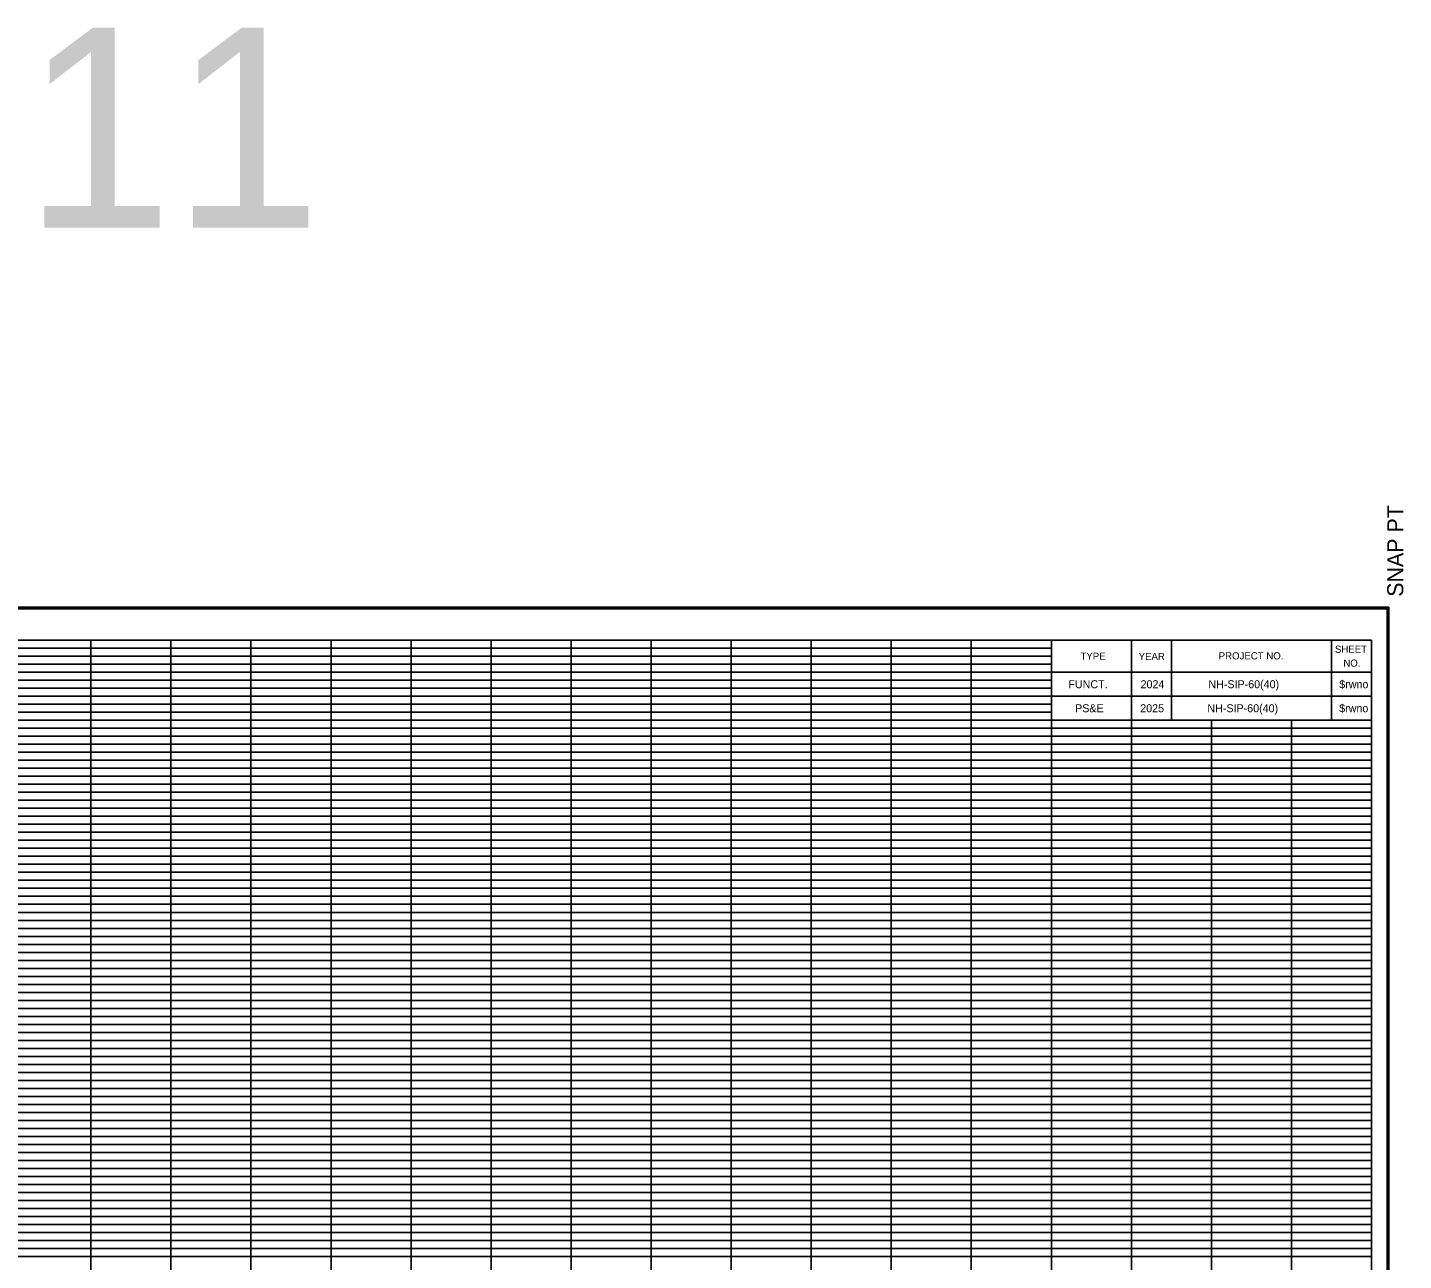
# Model space of a CAD drawing. Extents: x 2313580 to 2322968, y 282099 to 303247.
# Drawn here: x 2316394.2 to 2316738.1, y 287852.7 to 288160.8 of the extents above; entities that cross this region are included whole.
import ezdxf

# ---------------------------------------------------------------- set-up
doc = ezdxf.new("R2010")
doc.units = 0
for name, color, linetype in [('DESIGN - SCRATCH - User 1', 7, 'Continuous'), ('DESIGN - SHEET - Corner Text', 7, 'Continuous'), ('DESIGN - SHEET - Light Grid', 7, 'Continuous'), ('DESIGN - SHEET - Linework', 7, 'Continuous'), ('DESIGN - SHEET - Plot Shape', 7, 'Continuous')]:
    doc.layers.add(name, color=color, linetype=linetype)

msp = doc.modelspace()

# ---------------------------------------------------------------- linework, layer by layer
at = {"layer": 'DESIGN - SCRATCH - User 1'}
for p, q in [((2316660.08, 287996.67), (2316660.08, 287996.67)), ((2316674.88, 287996.67), (2316674.88, 287996.67)), ((2316699.88, 287996.67), (2316699.88, 287996.67)), ((2316724.88, 287996.67), (2316724.88, 287996.67)), ((2316660.08, 287990.67), (2316660.08, 287990.67)), ((2316674.88, 287990.67), (2316674.88, 287990.67)), ((2316699.88, 287990.67), (2316699.88, 287990.67)), ((2316724.88, 287990.67), (2316724.88, 287990.67))]:
    msp.add_line(p, q, dxfattribs=at)
at = {"layer": 'DESIGN - SHEET - Light Grid'}
for p, q in [((2316250.08, 288005.67), (2316410.08, 288005.67)), ((2316410.08, 288005.67), (2316570.08, 288005.67)), ((2316570.08, 288005.67), (2316650.08, 288005.67)), ((2316250.08, 288003.67), (2316410.08, 288003.67)), ((2316250.08, 288001.67), (2316410.08, 288001.67)), ((2316410.08, 288003.67), (2316570.08, 288003.67)), ((2316410.08, 288001.67), (2316570.08, 288001.67)), ((2316570.08, 288003.67), (2316650.08, 288003.67)), ((2316570.08, 288001.67), (2316650.08, 288001.67)), ((2316250.08, 287999.67), (2316410.08, 287999.67)), ((2316250.08, 287997.67), (2316410.08, 287997.67)), ((2316410.08, 287999.67), (2316570.08, 287999.67)), ((2316410.08, 287997.67), (2316570.08, 287997.67)), ((2316570.08, 287999.67), (2316650.08, 287999.67)), ((2316570.08, 287997.67), (2316650.08, 287997.67)), ((2316250.08, 287995.67), (2316410.08, 287995.67)), ((2316410.08, 287995.67), (2316570.08, 287995.67)), ((2316570.08, 287995.67), (2316650.08, 287995.67)), ((2316250.08, 287993.67), (2316410.08, 287993.67)), ((2316250.08, 287991.67), (2316410.08, 287991.67)), ((2316410.08, 287993.67), (2316570.08, 287993.67)), ((2316410.08, 287991.67), (2316570.08, 287991.67)), ((2316570.08, 287993.67), (2316650.08, 287993.67)), ((2316570.08, 287991.67), (2316650.08, 287991.67)), ((2316250.08, 287989.67), (2316410.08, 287989.67)), ((2316410.08, 287989.67), (2316570.08, 287989.67)), ((2316570.08, 287989.67), (2316650.08, 287989.67)), ((2316250.08, 287985.67), (2316410.08, 287985.67)), ((2316250.08, 287983.67), (2316410.08, 287983.67)), ((2316410.08, 287985.67), (2316570.08, 287985.67)), ((2316410.08, 287983.67), (2316570.08, 287983.67)), ((2316570.08, 287985.67), (2316730.08, 287985.67)), ((2316570.08, 287983.67), (2316730.08, 287983.67)), ((2316250.08, 287981.67), (2316410.08, 287981.67)), ((2316410.08, 287981.67), (2316570.08, 287981.67)), ((2316570.08, 287981.67), (2316730.08, 287981.67)), ((2316250.08, 287979.67), (2316410.08, 287979.67)), ((2316250.08, 287977.67), (2316410.08, 287977.67)), ((2316410.08, 287979.67), (2316570.08, 287979.67)), ((2316410.08, 287977.67), (2316570.08, 287977.67)), ((2316570.08, 287979.67), (2316730.08, 287979.67)), ((2316570.08, 287977.67), (2316730.08, 287977.67)), ((2316250.08, 287975.67), (2316410.08, 287975.67)), ((2316250.08, 287973.67), (2316410.08, 287973.67)), ((2316410.08, 287975.67), (2316570.08, 287975.67)), ((2316410.08, 287973.67), (2316570.08, 287973.67)), ((2316570.08, 287975.67), (2316730.08, 287975.67)), ((2316570.08, 287973.67), (2316730.08, 287973.67)), ((2316250.08, 287971.67), (2316410.08, 287971.67)), ((2316250.08, 287969.67), (2316410.08, 287969.67)), ((2316410.08, 287971.67), (2316570.08, 287971.67)), ((2316410.08, 287969.67), (2316570.08, 287969.67)), ((2316570.08, 287971.67), (2316730.08, 287971.67)), ((2316570.08, 287969.67), (2316730.08, 287969.67)), ((2316250.08, 287965.67), (2316410.08, 287965.67)), ((2316250.08, 287963.67), (2316410.08, 287963.67)), ((2316410.08, 287965.67), (2316570.08, 287965.67)), ((2316410.08, 287963.67), (2316570.08, 287963.67)), ((2316570.08, 287965.67), (2316730.08, 287965.67)), ((2316570.08, 287963.67), (2316730.08, 287963.67)), ((2316250.08, 287961.67), (2316410.08, 287961.67)), ((2316250.08, 287959.67), (2316410.08, 287959.67)), ((2316410.08, 287961.67), (2316570.08, 287961.67)), ((2316410.08, 287959.67), (2316570.08, 287959.67)), ((2316570.08, 287961.67), (2316730.08, 287961.67)), ((2316570.08, 287959.67), (2316730.08, 287959.67)), ((2316250.08, 287957.67), (2316410.08, 287957.67)), ((2316410.08, 287957.67), (2316570.08, 287957.67)), ((2316570.08, 287957.67), (2316730.08, 287957.67)), ((2316250.08, 287955.67), (2316410.08, 287955.67)), ((2316250.08, 287953.67), (2316410.08, 287953.67)), ((2316410.08, 287955.67), (2316570.08, 287955.67)), ((2316410.08, 287953.67), (2316570.08, 287953.67)), ((2316570.08, 287955.67), (2316730.08, 287955.67)), ((2316570.08, 287953.67), (2316730.08, 287953.67)), ((2316250.08, 287951.67), (2316410.08, 287951.67)), ((2316250.08, 287949.67), (2316410.08, 287949.67)), ((2316410.08, 287951.67), (2316570.08, 287951.67)), ((2316410.08, 287949.67), (2316570.08, 287949.67)), ((2316570.08, 287951.67), (2316730.08, 287951.67)), ((2316570.08, 287949.67), (2316730.08, 287949.67)), ((2316250.08, 287945.67), (2316410.08, 287945.67)), ((2316410.08, 287945.67), (2316570.08, 287945.67)), ((2316570.08, 287945.67), (2316730.08, 287945.67)), ((2316250.08, 287943.67), (2316410.08, 287943.67)), ((2316410.08, 287943.67), (2316570.08, 287943.67)), ((2316570.08, 287943.67), (2316730.08, 287943.67)), ((2316250.08, 287941.67), (2316410.08, 287941.67)), ((2316250.08, 287939.67), (2316410.08, 287939.67)), ((2316410.08, 287941.67), (2316570.08, 287941.67)), ((2316410.08, 287939.67), (2316570.08, 287939.67)), ((2316570.08, 287941.67), (2316730.08, 287941.67)), ((2316570.08, 287939.67), (2316730.08, 287939.67)), ((2316250.08, 287937.67), (2316410.08, 287937.67)), ((2316250.08, 287935.67), (2316410.08, 287935.67)), ((2316410.08, 287937.67), (2316570.08, 287937.67)), ((2316410.08, 287935.67), (2316570.08, 287935.67)), ((2316570.08, 287937.67), (2316730.08, 287937.67)), ((2316570.08, 287935.67), (2316730.08, 287935.67)), ((2316250.08, 287933.67), (2316410.08, 287933.67)), ((2316410.08, 287933.67), (2316570.08, 287933.67)), ((2316570.08, 287933.67), (2316730.08, 287933.67)), ((2316250.08, 287931.67), (2316410.08, 287931.67)), ((2316250.08, 287929.67), (2316410.08, 287929.67)), ((2316410.08, 287931.67), (2316570.08, 287931.67)), ((2316410.08, 287929.67), (2316570.08, 287929.67)), ((2316570.08, 287931.67), (2316730.08, 287931.67)), ((2316570.08, 287929.67), (2316730.08, 287929.67)), ((2316250.08, 287925.67), (2316410.08, 287925.67)), ((2316410.08, 287925.67), (2316570.08, 287925.67)), ((2316570.08, 287925.67), (2316730.08, 287925.67)), ((2316250.08, 287923.67), (2316410.08, 287923.67)), ((2316250.08, 287921.67), (2316410.08, 287921.67)), ((2316410.08, 287923.67), (2316570.08, 287923.67)), ((2316410.08, 287921.67), (2316570.08, 287921.67)), ((2316570.08, 287923.67), (2316730.08, 287923.67)), ((2316570.08, 287921.67), (2316730.08, 287921.67)), ((2316250.08, 287919.67), (2316410.08, 287919.67)), ((2316410.08, 287919.67), (2316570.08, 287919.67)), ((2316570.08, 287919.67), (2316730.08, 287919.67)), ((2316250.08, 287917.67), (2316410.08, 287917.67)), ((2316250.08, 287915.67), (2316410.08, 287915.67)), ((2316410.08, 287917.67), (2316570.08, 287917.67)), ((2316410.08, 287915.67), (2316570.08, 287915.67)), ((2316570.08, 287917.67), (2316730.08, 287917.67)), ((2316570.08, 287915.67), (2316730.08, 287915.67)), ((2316250.08, 287913.67), (2316410.08, 287913.67)), ((2316250.08, 287911.67), (2316410.08, 287911.67)), ((2316410.08, 287913.67), (2316570.08, 287913.67)), ((2316410.08, 287911.67), (2316570.08, 287911.67)), ((2316570.08, 287913.67), (2316730.08, 287913.67)), ((2316570.08, 287911.67), (2316730.08, 287911.67)), ((2316250.08, 287909.67), (2316410.08, 287909.67)), ((2316410.08, 287909.67), (2316570.08, 287909.67)), ((2316570.08, 287909.67), (2316730.08, 287909.67)), ((2316250.08, 287905.67), (2316410.08, 287905.67)), ((2316410.08, 287905.67), (2316570.08, 287905.67)), ((2316570.08, 287905.67), (2316730.08, 287905.67)), ((2316250.08, 287903.67), (2316410.08, 287903.67)), ((2316250.08, 287901.67), (2316410.08, 287901.67)), ((2316410.08, 287903.67), (2316570.08, 287903.67)), ((2316410.08, 287901.67), (2316570.08, 287901.67)), ((2316570.08, 287903.67), (2316730.08, 287903.67)), ((2316570.08, 287901.67), (2316730.08, 287901.67)), ((2316250.08, 287899.67), (2316410.08, 287899.67)), ((2316250.08, 287897.67), (2316410.08, 287897.67)), ((2316410.08, 287899.67), (2316570.08, 287899.67)), ((2316410.08, 287897.67), (2316570.08, 287897.67)), ((2316570.08, 287899.67), (2316730.08, 287899.67)), ((2316570.08, 287897.67), (2316730.08, 287897.67)), ((2316250.08, 287895.67), (2316410.08, 287895.67)), ((2316410.08, 287895.67), (2316570.08, 287895.67)), ((2316570.08, 287895.67), (2316730.08, 287895.67)), ((2316250.08, 287893.67), (2316410.08, 287893.67)), ((2316250.08, 287891.67), (2316410.08, 287891.67)), ((2316410.08, 287893.67), (2316570.08, 287893.67)), ((2316410.08, 287891.67), (2316570.08, 287891.67)), ((2316570.08, 287893.67), (2316730.08, 287893.67)), ((2316570.08, 287891.67), (2316730.08, 287891.67)), ((2316250.08, 287889.67), (2316410.08, 287889.67)), ((2316410.08, 287889.67), (2316570.08, 287889.67)), ((2316570.08, 287889.67), (2316730.08, 287889.67)), ((2316250.08, 287885.67), (2316410.08, 287885.67)), ((2316410.08, 287885.67), (2316570.08, 287885.67)), ((2316570.08, 287885.67), (2316730.08, 287885.67)), ((2316250.08, 287883.67), (2316410.08, 287883.67)), ((2316250.08, 287881.67), (2316410.08, 287881.67)), ((2316410.08, 287883.67), (2316570.08, 287883.67)), ((2316410.08, 287881.67), (2316570.08, 287881.67)), ((2316570.08, 287883.67), (2316730.08, 287883.67)), ((2316570.08, 287881.67), (2316730.08, 287881.67)), ((2316250.08, 287879.67), (2316410.08, 287879.67)), ((2316250.08, 287877.67), (2316410.08, 287877.67)), ((2316410.08, 287879.67), (2316570.08, 287879.67)), ((2316410.08, 287877.67), (2316570.08, 287877.67)), ((2316570.08, 287879.67), (2316730.08, 287879.67)), ((2316570.08, 287877.67), (2316730.08, 287877.67)), ((2316250.08, 287875.67), (2316410.08, 287875.67)), ((2316250.08, 287873.67), (2316410.08, 287873.67)), ((2316410.08, 287875.67), (2316570.08, 287875.67)), ((2316410.08, 287873.67), (2316570.08, 287873.67)), ((2316570.08, 287875.67), (2316730.08, 287875.67)), ((2316570.08, 287873.67), (2316730.08, 287873.67)), ((2316250.08, 287871.67), (2316410.08, 287871.67)), ((2316410.08, 287871.67), (2316570.08, 287871.67)), ((2316570.08, 287871.67), (2316730.08, 287871.67)), ((2316250.08, 287869.67), (2316410.08, 287869.67)), ((2316410.08, 287869.67), (2316570.08, 287869.67)), ((2316570.08, 287869.67), (2316730.08, 287869.67)), ((2316250.08, 287865.67), (2316410.08, 287865.67)), ((2316250.08, 287863.67), (2316410.08, 287863.67)), ((2316410.08, 287865.67), (2316570.08, 287865.67)), ((2316410.08, 287863.67), (2316570.08, 287863.67)), ((2316570.08, 287865.67), (2316730.08, 287865.67)), ((2316570.08, 287863.67), (2316730.08, 287863.67)), ((2316250.08, 287861.67), (2316410.08, 287861.67)), ((2316250.08, 287859.67), (2316410.08, 287859.67)), ((2316410.08, 287861.67), (2316570.08, 287861.67)), ((2316410.08, 287859.67), (2316570.08, 287859.67)), ((2316570.08, 287861.67), (2316730.08, 287861.67)), ((2316570.08, 287859.67), (2316730.08, 287859.67)), ((2316250.08, 287857.67), (2316410.08, 287857.67)), ((2316410.08, 287857.67), (2316570.08, 287857.67)), ((2316570.08, 287857.67), (2316730.08, 287857.67)), ((2316250.08, 287855.67), (2316410.08, 287855.67)), ((2316250.08, 287853.67), (2316410.08, 287853.67)), ((2316410.08, 287855.67), (2316570.08, 287855.67)), ((2316410.08, 287853.67), (2316570.08, 287853.67)), ((2316570.08, 287855.67), (2316730.08, 287855.67)), ((2316570.08, 287853.67), (2316730.08, 287853.67))]:
    msp.add_line(p, q, dxfattribs=at)
at = {"layer": 'DESIGN - SHEET - Linework'}
for p, q in [((2316053.62, 288015.95), (2316734.42, 288015.95)), ((2316734.42, 288015.95), (2316734.42, 287579.39)), ((2316410.08, 287587.67), (2316410.08, 288007.67)), ((2316430.08, 287587.67), (2316430.08, 288007.67)), ((2316450.08, 287587.67), (2316450.08, 288007.67)), ((2316470.08, 287587.67), (2316470.08, 288007.67)), ((2316490.08, 287587.67), (2316490.08, 288007.67)), ((2316510.08, 287587.67), (2316510.08, 288007.67)), ((2316530.08, 287587.67), (2316530.08, 288007.67)), ((2316550.08, 287587.67), (2316550.08, 288007.67)), ((2316570.08, 287587.67), (2316570.08, 288007.67)), ((2316590.08, 287587.67), (2316590.08, 288007.67)), ((2316610.08, 287587.67), (2316610.08, 288007.67)), ((2316630.08, 287587.67), (2316630.08, 288007.67)), ((2316090.08, 287987.67), (2316650.08, 287987.67)), ((2316650.08, 287587.67), (2316650.08, 287987.67)), ((2316670.08, 287587.67), (2316670.08, 287987.67)), ((2316690.08, 287587.67), (2316690.08, 287987.67)), ((2316710.08, 287587.67), (2316710.08, 287987.67)), ((2316090.08, 287967.67), (2316730.08, 287967.67)), ((2316090.08, 287947.67), (2316730.08, 287947.67)), ((2316090.08, 287927.67), (2316730.08, 287927.67)), ((2316090.08, 287907.67), (2316730.08, 287907.67)), ((2316090.08, 287887.67), (2316730.08, 287887.67)), ((2316090.08, 287867.67), (2316730.08, 287867.67))]:
    msp.add_line(p, q, dxfattribs=at)
for points in [[(2316090.08, 288007.67), (2316090.08, 287587.67), (2316730.08, 287587.67), (2316730.08, 288007.67), (2316090.08, 288007.67)], [(2316650.08, 288007.67), (2316650.08, 287987.67), (2316730.08, 287987.67), (2316730.08, 288007.67), (2316720.08, 288007.67), (2316720.08, 287987.67), (2316680.08, 287987.67), (2316680.08, 288007.67), (2316670.08, 288007.67), (2316670.08, 287987.67), (2316730.08, 287987.67), (2316650.08, 287987.67), (2316650.08, 287993.67), (2316730.08, 287993.67), (2316730.08, 287999.67), (2316650.08, 287999.67)]]:
    msp.add_lwpolyline(points, dxfattribs=at)
at = {"layer": 'DESIGN - SHEET - Plot Shape'}
for points in [[(2316054.02, 288015.55), (2316734.02, 288015.55), (2316734.02, 287579.79), (2316054.02, 287579.79)], [(2316073.08, 288007.67), (2316730.08, 288007.67), (2316730.08, 287582.67), (2316073.08, 287582.67)]]:
    msp.add_lwpolyline(points, close=True, dxfattribs=at)

# ---------------------------------------------------------------- texts
at = {"layer": 'DESIGN - SCRATCH - User 1'}
msp.add_text('11', height=50, dxfattribs=at).set_placement((2316393.31, 288110.78))
at = {"layer": 'DESIGN - SHEET - Corner Text'}
for s, height, rotation, p in [('  SNAP PT', 4, 90, (2316738.02, 288015.55)), ('TYPE', 1.8, 360, (2316657.36, 288002.79)), ('YEAR', 1.8, 360, (2316671.89, 288002.71)), ('PROJECT NO.', 1.8, 360, (2316691.9, 288002.87)), ('SHEET', 1.8, 360, (2316720.94, 288004.53)), ('NO.', 1.8, 360, (2316723.05, 288001.05)), ('  FUNCT.   ', 2, 360, (2316652.85, 287995.67)), ('2024', 2, 360, (2316672.38, 287995.67))]:
    msp.add_text(s, height=height, rotation=rotation, dxfattribs=at).set_placement(p)
for s, p in [('   NH-SIP-60(40)    ', (2316687.09, 287995.67)), ('$rwno', (2316722.03, 287995.67)), (' PS&E ', (2316655.27, 287989.67)), ('2025', (2316672.3, 287989.67)), ('   NH-SIP-60(40)    ', (2316686.84, 287989.67)), ('$rwno', (2316722.01, 287989.67))]:
    msp.add_text(s, height=2, dxfattribs=at).set_placement(p)

doc.saveas('drawing.dxf')
